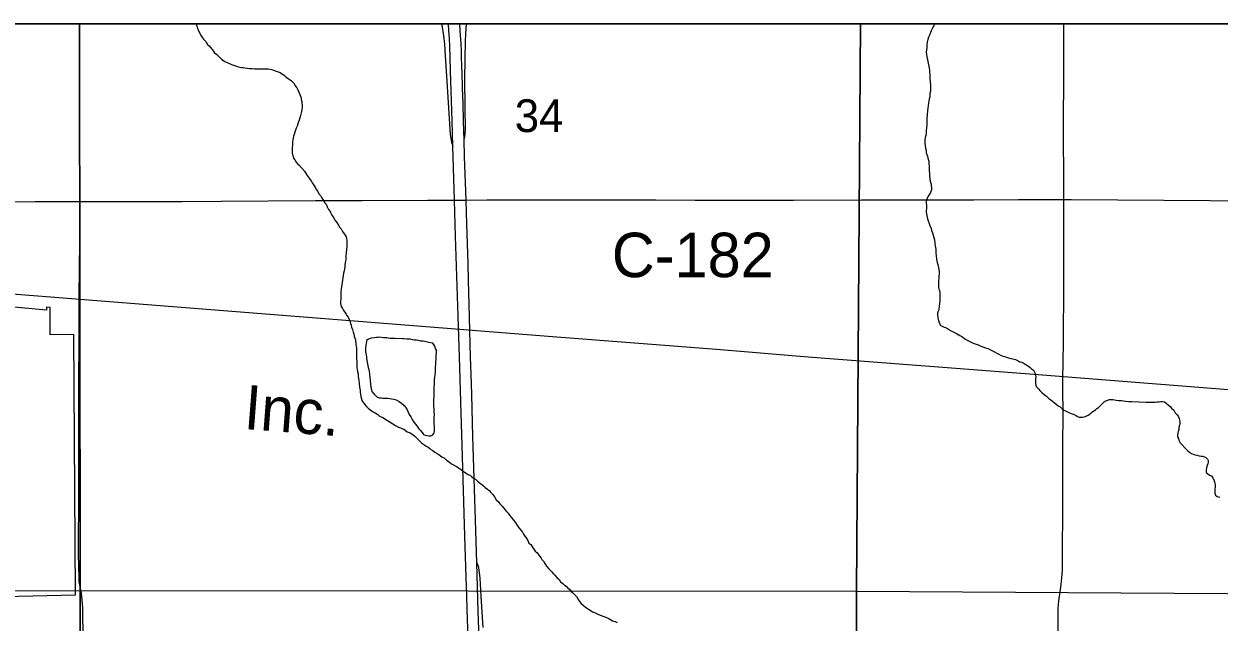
# Model space of a CAD drawing. Extents: x -17 to 88, y -5 to 22.
# Drawn here: x 5.65 to 7.178, y 20.136 to 20.9 of the extents above; entities that cross this region are included whole.
import ezdxf

# ---------------------------------------------------------------- set-up
doc = ezdxf.new("R2010")
doc.units = 0
for name, color, linetype in [('GM_X_Corporation', 7, 'Continuous'), ('GM_X_County_Road', 7, 'Continuous'), ('GM_X_County_Road_Text', 7, 'Continuous'), ('GM_X_Interchange_Ramps', 7, 'Continuous'), ('GM_X_Minor_Lake', 7, 'Continuous'), ('GM_X_Minor_River', 7, 'Continuous'), ('GM_X_Rail_Line', 7, 'Continuous'), ('GM_X_Rail_Line_Text', 7, 'Continuous'), ('GM_X_Section', 7, 'Continuous'), ('GM_X_Section_Text', 7, 'Continuous'), ('GM_X_Township', 7, 'Continuous'), ('GM_X_Township_Road', 7, 'Continuous'), ('GM_X_US_Route', 7, 'Continuous'), ('SH_Data', 7, 'Continuous')]:
    doc.layers.add(name, color=color, linetype=linetype)

msp = doc.modelspace()

# ---------------------------------------------------------------- linework, layer by layer
at = {"layer": 'GM_X_Corporation'}
msp.add_lwpolyline([(5.443, 20.164), (5.7163, 20.1707), (5.7142, 20.5031), (5.6839, 20.5029), (5.6839, 20.5377), (5.6792, 20.5381), (5.6792, 20.5343), (5.5358, 20.5474)], dxfattribs=at)
at = {"layer": 'GM_X_County_Road'}
for points in [[(5.5874, 20.6724), (5.665, 20.6729), (5.7221, 20.6729)], [(5.7221, 20.6729), (5.7678, 20.673), (5.8123, 20.6732), (5.8529, 20.6732), (5.9026, 20.6734), (6.0231, 20.6743), (6.0828, 20.6742), (6.1663, 20.6748), (6.2009, 20.6749), (6.2155, 20.675), (6.242, 20.6752), (6.2872, 20.6753), (6.3838, 20.6751), (6.4581, 20.6751), (6.5085, 20.6748), (6.5557, 20.6747), (6.634, 20.6747), (6.7207, 20.6753), (6.7882, 20.6753), (6.8646, 20.6754), (6.9217, 20.6755), (6.9796, 20.6755)], [(6.9796, 20.6755), (6.9889, 20.6755), (7.0485, 20.6752), (7.1659, 20.6744), (7.2076, 20.6741), (7.2512, 20.6738), (7.3034, 20.6736), (7.3543, 20.6734), (7.4103, 20.6735), (7.5085, 20.6729), (7.5401, 20.6726), (7.5694, 20.6725), (7.6306, 20.6723), (7.6964, 20.6717), (7.721, 20.6718)]]:
    msp.add_lwpolyline(points, dxfattribs=at)
at = {"layer": 'GM_X_Interchange_Ramps'}
for points in [[(6.1842, 20.9), (6.1846, 20.8983), (6.1866, 20.8848), (6.1878, 20.8743), (6.189, 20.8594), (6.1905, 20.8334), (6.1952, 20.7586), (6.196, 20.7535), (6.1969, 20.7489), (6.1987, 20.7439)], [(6.2129, 20.7517), (6.214, 20.7555), (6.2145, 20.7595), (6.2149, 20.7657), (6.2144, 20.7927), (6.2141, 20.8298), (6.2141, 20.8381), (6.2142, 20.8468), (6.2143, 20.8555), (6.2145, 20.8632), (6.2148, 20.8704), (6.215, 20.8779), (6.2154, 20.8872), (6.216, 20.9)]]:
    msp.add_lwpolyline(points, dxfattribs=at)
at = {"layer": 'GM_X_Minor_Lake'}
for points in [[(6.1046, 20.4221), (6.1069, 20.4221), (6.1092, 20.422), (6.1111, 20.4216), (6.113, 20.4216), (6.1153, 20.4216), (6.1179, 20.4215), (6.1202, 20.4211), (6.1232, 20.4206), (6.1251, 20.4199), (6.127, 20.4191), (6.13, 20.4175), (6.133, 20.4155), (6.1364, 20.4124), (6.139, 20.409), (6.1401, 20.407), (6.1416, 20.404), (6.143, 20.4009), (6.1449, 20.3978), (6.1467, 20.3944), (6.1489, 20.3913), (6.1515, 20.3882), (6.1534, 20.3852), (6.1552, 20.3828), (6.1567, 20.3809), (6.1593, 20.3778), (6.1612, 20.3755), (6.1631, 20.3747), (6.168, 20.3735), (6.1707, 20.3738), (6.173, 20.3749), (6.1749, 20.3775), (6.1753, 20.3794), (6.1754, 20.3813), (6.175, 20.3844), (6.1751, 20.3866), (6.1747, 20.3889), (6.1748, 20.3935), (6.1749, 20.3958), (6.1749, 20.398), (6.175, 20.4007), (6.1746, 20.4045), (6.1747, 20.4064), (6.1747, 20.4087), (6.1744, 20.411), (6.1744, 20.4132), (6.1745, 20.4167), (6.1745, 20.4189), (6.1742, 20.4212), (6.1746, 20.4231), (6.1747, 20.4254), (6.1747, 20.4288), (6.1748, 20.4315), (6.1748, 20.4334), (6.1754, 20.4421), (6.1754, 20.4459), (6.1758, 20.4482), (6.1759, 20.4516), (6.1764, 20.455), (6.1764, 20.4588), (6.1765, 20.4618), (6.1769, 20.4648), (6.177, 20.4683), (6.1774, 20.4713), (6.1775, 20.4743), (6.1775, 20.4766), (6.1776, 20.4793), (6.1776, 20.4831), (6.1765, 20.4854), (6.1755, 20.4884), (6.1729, 20.4919), (6.1702, 20.4927), (6.1679, 20.4931), (6.1645, 20.4939), (6.1626, 20.4943), (6.1607, 20.4948), (6.1577, 20.4948), (6.1547, 20.4953), (6.152, 20.4961), (6.1494, 20.4961), (6.1475, 20.4965), (6.1444, 20.497), (6.1422, 20.497), (6.1399, 20.4974), (6.1361, 20.4975), (6.1338, 20.4975), (6.1247, 20.4981), (6.1228, 20.4981), (6.1209, 20.4982), (6.1186, 20.4982), (6.116, 20.4986), (6.1141, 20.499), (6.1118, 20.4991), (6.1099, 20.4991), (6.1072, 20.4992), (6.1053, 20.4996), (6.103, 20.4993), (6.1011, 20.4993), (6.0981, 20.499), (6.0943, 20.4983), (6.0889, 20.4965)], [(6.0889, 20.4965), (6.0873, 20.4897), (6.0868, 20.4855), (6.0872, 20.4836), (6.0871, 20.4809), (6.0878, 20.4771), (6.0881, 20.4745), (6.0885, 20.4726), (6.0902, 20.463), (6.0905, 20.4608), (6.0913, 20.4585), (6.0916, 20.4558), (6.0923, 20.4524), (6.0926, 20.4482), (6.0929, 20.444), (6.0932, 20.4398), (6.0939, 20.436), (6.0946, 20.433), (6.0953, 20.4303), (6.0979, 20.4268), (6.1016, 20.4233), (6.1046, 20.4221)]]:
    msp.add_lwpolyline(points, dxfattribs=at)
at = {"layer": 'GM_X_Minor_River'}
for points in [[(5.8706, 20.9), (5.871, 20.8981), (5.8717, 20.8962), (5.8724, 20.8943), (5.8731, 20.8924), (5.8739, 20.8905), (5.8772, 20.8847), (5.8787, 20.8824), (5.8801, 20.8805), (5.8828, 20.8774), (5.8853, 20.8739), (5.8872, 20.872), (5.8891, 20.8697), (5.8913, 20.867), (5.8939, 20.8631), (5.8969, 20.8608), (5.8995, 20.8585), (5.9017, 20.8562), (5.9036, 20.8546), (5.9055, 20.8534), (5.9074, 20.8519), (5.9093, 20.8511), (5.9111, 20.8503), (5.913, 20.8495), (5.9157, 20.8483), (5.9183, 20.8471), (5.9221, 20.8459), (5.9243, 20.8451), (5.9266, 20.8447), (5.9285, 20.8443), (5.9308, 20.8442), (5.9327, 20.8438), (5.9357, 20.8434), (5.9388, 20.8429), (5.9422, 20.8429), (5.9456, 20.8424), (5.949, 20.8424), (5.9524, 20.8427), (5.957, 20.8426), (5.96, 20.8425), (5.9627, 20.8425), (5.965, 20.8421), (5.9672, 20.8417), (5.9695, 20.8408), (5.9714, 20.8401), (5.974, 20.8392), (5.9778, 20.8377), (5.9797, 20.8365), (5.9816, 20.8353), (5.9835, 20.8341), (5.9853, 20.8322), (5.9924, 20.8271), (5.9954, 20.8244), (5.9976, 20.8206)], [(6.8143, 20.9), (6.8143, 20.9), (6.8131, 20.8977), (6.8119, 20.8958), (6.8111, 20.8936), (6.8099, 20.8913), (6.8091, 20.889), (6.8079, 20.8857), (6.8063, 20.883), (6.8055, 20.88), (6.8047, 20.8766), (6.8043, 20.8732), (6.8042, 20.8698), (6.8038, 20.8667), (6.8037, 20.8641), (6.804, 20.861), (6.8044, 20.858), (6.805, 20.8542), (6.8061, 20.85), (6.8068, 20.8458), (6.8075, 20.8431), (6.8078, 20.8412), (6.8078, 20.8386), (6.8081, 20.8351), (6.8081, 20.8325), (6.8084, 20.8298), (6.8087, 20.826), (6.809, 20.8222), (6.8089, 20.8188), (6.8089, 20.8165), (6.8089, 20.8142), (6.8084, 20.8116), (6.8084, 20.8093), (6.808, 20.807), (6.8075, 20.8044), (6.8071, 20.8017), (6.8067, 20.7991), (6.8062, 20.7957), (6.8058, 20.7923), (6.8054, 20.7892), (6.8044, 20.7786), (6.8043, 20.7748), (6.8043, 20.771), (6.8038, 20.7672), (6.8037, 20.7638), (6.8033, 20.7604), (6.8029, 20.7574), (6.8024, 20.7547), (6.802, 20.7525), (6.802, 20.7498), (6.8019, 20.7472), (6.8022, 20.7441), (6.8026, 20.7414), (6.8033, 20.7384), (6.8036, 20.7354), (6.8043, 20.7331), (6.805, 20.7311), (6.8057, 20.7285), (6.8068, 20.7247), (6.8071, 20.7212), (6.8074, 20.7178), (6.8074, 20.7152), (6.8073, 20.7117)], [(5.9976, 20.8206), (5.9991, 20.8183), (6.0006, 20.8156), (6.0017, 20.8129), (6.0032, 20.8098), (6.0039, 20.8076), (6.0046, 20.8056), (6.0049, 20.8034), (6.0056, 20.8007), (6.0056, 20.7988), (6.0059, 20.7965), (6.0059, 20.7938), (6.0058, 20.7904), (6.0054, 20.7882), (6.005, 20.7863), (6.0038, 20.7829), (6.003, 20.7802), (6.0022, 20.7772), (6.0014, 20.7749), (6.0005, 20.7723), (5.9997, 20.7693), (5.9985, 20.7666), (5.9974, 20.7644), (5.9965, 20.7617), (5.9957, 20.7587), (5.9949, 20.7565), (5.9945, 20.7538), (5.9941, 20.7515), (5.9937, 20.7496), (5.9936, 20.7474), (5.9936, 20.7447), (5.9935, 20.742), (5.9931, 20.7394), (5.9931, 20.7375), (5.9934, 20.7348), (5.9944, 20.7306), (5.9952, 20.7283), (5.9967, 20.7264), (5.9985, 20.7233), (6.0004, 20.721), (6.0022, 20.7195), (6.0089, 20.7118), (6.0104, 20.7098), (6.0126, 20.7064), (6.0141, 20.7041), (6.016, 20.7018), (6.0174, 20.6995), (6.0189, 20.6971), (6.02, 20.6952), (6.0215, 20.6929), (6.023, 20.6906), (6.0241, 20.6883), (6.0259, 20.686), (6.0274, 20.6829), (6.0293, 20.6806), (6.0307, 20.6783), (6.0322, 20.676), (6.0337, 20.6741), (6.0348, 20.6718), (6.0366, 20.6695), (6.0381, 20.6664), (6.0396, 20.663), (6.0418, 20.6603), (6.0429, 20.6583), (6.044, 20.6557), (6.0455, 20.6537), (6.0473, 20.6507), (6.0484, 20.6487), (6.0503, 20.6461), (6.0525, 20.643), (6.0543, 20.6399), (6.0558, 20.638), (6.0577, 20.6349), (6.0599, 20.6318), (6.061, 20.6299), (6.0621, 20.628), (6.0628, 20.6257), (6.0632, 20.6234), (6.063, 20.6154), (6.0626, 20.612), (6.0621, 20.6075), (6.062, 20.6033), (6.0619, 20.5984), (6.0611, 20.595), (6.0607, 20.5923), (6.0606, 20.5893), (6.0602, 20.587), (6.0598, 20.5847), (6.059, 20.5817), (6.0585, 20.5787), (6.0581, 20.5757), (6.0577, 20.5726), (6.0572, 20.5696), (6.0568, 20.5666), (6.0564, 20.5643), (6.0559, 20.5613), (6.0555, 20.5579), (6.0554, 20.5556), (6.0554, 20.5533), (6.0553, 20.5506), (6.0553, 20.548)], [(6.8073, 20.7117), (6.8077, 20.7091), (6.8076, 20.7057), (6.8083, 20.7022), (6.8086, 20.6992), (6.8097, 20.6954), (6.81, 20.6931), (6.8104, 20.6908), (6.8103, 20.6881), (6.8091, 20.6844), (6.8068, 20.681), (6.8052, 20.678), (6.8044, 20.6761), (6.8036, 20.6731), (6.8035, 20.6712), (6.8038, 20.6678), (6.8038, 20.6643), (6.8037, 20.6617), (6.8037, 20.6598), (6.804, 20.6575), (6.8054, 20.651), (6.8061, 20.6483), (6.8072, 20.6449), (6.8083, 20.6418), (6.8098, 20.6392), (6.8105, 20.6361), (6.8116, 20.6331), (6.8123, 20.63), (6.8134, 20.6273), (6.814, 20.6239), (6.8147, 20.6197), (6.815, 20.6163), (6.8157, 20.6121), (6.816, 20.6075), (6.8163, 20.6033), (6.8166, 20.5999), (6.8173, 20.5969), (6.818, 20.5938), (6.8188, 20.5915), (6.8191, 20.5881), (6.8198, 20.5858), (6.8201, 20.5835), (6.8201, 20.5809), (6.8196, 20.5775), (6.8196, 20.5748), (6.8192, 20.5721), (6.8191, 20.5691), (6.8191, 20.5665), (6.8194, 20.5638), (6.8197, 20.5611), (6.8204, 20.5592), (6.8208, 20.5566), (6.8211, 20.552), (6.821, 20.5493), (6.821, 20.5463), (6.8205, 20.5429), (6.8201, 20.5391), (6.8196, 20.5357), (6.8192, 20.5338), (6.8184, 20.5319), (6.818, 20.53), (6.818, 20.5277), (6.8183, 20.5247), (6.819, 20.5224), (6.8197, 20.5197), (6.8219, 20.5148), (6.8238, 20.5136), (6.8264, 20.5124), (6.8283, 20.512), (6.8306, 20.5108), (6.8347, 20.5084), (6.8388, 20.5061), (6.8422, 20.5045), (6.8445, 20.5033), (6.8467, 20.5018), (6.849, 20.5006), (6.8509, 20.4994), (6.8531, 20.4978), (6.8561, 20.4959), (6.8595, 20.4943), (6.8629, 20.4927), (6.8663, 20.4911), (6.8701, 20.4899), (6.8727, 20.4888), (6.8758, 20.4876), (6.8795, 20.4863), (6.8826, 20.4851), (6.8856, 20.4836), (6.8882, 20.4824), (6.8908, 20.4808), (6.8938, 20.4792), (6.8965, 20.4781), (6.8995, 20.4765), (6.9048, 20.4745), (6.9086, 20.4733), (6.9116, 20.4725), (6.9142, 20.472), (6.9176, 20.4712), (6.921, 20.4696), (6.9233, 20.4684), (6.9256, 20.4676)], [(6.0553, 20.548), (6.0552, 20.5453), (6.0552, 20.5427), (6.0559, 20.5389), (6.0577, 20.5362), (6.0588, 20.5339), (6.0607, 20.5316), (6.0625, 20.5292), (6.0633, 20.5273), (6.0648, 20.5254), (6.0673, 20.5193), (6.068, 20.5174), (6.0687, 20.5151), (6.0691, 20.5124), (6.0702, 20.5094), (6.0712, 20.5063), (6.072, 20.504), (6.0727, 20.501), (6.0734, 20.4983), (6.0741, 20.4964), (6.0744, 20.4945), (6.0748, 20.4926), (6.0747, 20.4903), (6.0751, 20.488), (6.0754, 20.4861), (6.0754, 20.4834), (6.0753, 20.4808), (6.0756, 20.4777), (6.0756, 20.4751), (6.0755, 20.472), (6.0759, 20.4694), (6.0758, 20.4663), (6.0758, 20.4637), (6.0761, 20.4606), (6.0764, 20.4587), (6.0768, 20.4557), (6.0775, 20.453), (6.0778, 20.4511), (6.0778, 20.4492), (6.0781, 20.4469), (6.0785, 20.4446), (6.0788, 20.4405), (6.0794, 20.4359), (6.0801, 20.4317), (6.0804, 20.429), (6.0808, 20.4268), (6.0811, 20.4241), (6.0818, 20.421), (6.0825, 20.4187), (6.0859, 20.4141), (6.0885, 20.411), (6.0903, 20.4091), (6.0922, 20.4079), (6.0948, 20.4056), (6.0967, 20.4044), (6.0993, 20.4029), (6.1027, 20.4009), (6.105, 20.399), (6.1072, 20.3978), (6.1099, 20.3966), (6.1117, 20.3954), (6.1151, 20.3931), (6.1185, 20.3911), (6.1219, 20.3892), (6.1253, 20.3868), (6.129, 20.3848), (6.1317, 20.3837), (6.1336, 20.3829), (6.1358, 20.3821), (6.1377, 20.3809), (6.1403, 20.3789), (6.1441, 20.3774), (6.1464, 20.3762), (6.1501, 20.3731), (6.1535, 20.37), (6.1557, 20.3676), (6.1583, 20.3653), (6.1602, 20.3634), (6.1628, 20.3618), (6.1647, 20.3606), (6.167, 20.3591), (6.1688, 20.3579), (6.1707, 20.3564), (6.173, 20.3548), (6.1756, 20.3528), (6.1786, 20.3513), (6.1812, 20.3493), (6.1846, 20.347), (6.188, 20.345), (6.1906, 20.3427), (6.194, 20.3403), (6.197, 20.338), (6.2041, 20.3341), (6.2071, 20.3321), (6.2098, 20.3302), (6.212, 20.3286), (6.215, 20.3263), (6.218, 20.3243), (6.221, 20.3228), (6.2229, 20.3212), (6.2248, 20.32)], [(6.9256, 20.4676), (6.9275, 20.4668), (6.9301, 20.4653), (6.932, 20.4641), (6.9342, 20.4629), (6.9365, 20.461), (6.9387, 20.459), (6.9406, 20.4575), (6.9421, 20.4552), (6.9428, 20.4533), (6.9431, 20.4514), (6.9435, 20.4491), (6.9434, 20.446), (6.9433, 20.4422), (6.9433, 20.4404), (6.9437, 20.4384), (6.9447, 20.4361), (6.9474, 20.4334), (6.9488, 20.4315), (6.9515, 20.4292), (6.9541, 20.4265), (6.9571, 20.4245), (6.9604, 20.4214), (6.9627, 20.4195), (6.9649, 20.4179), (6.9672, 20.4164), (6.9698, 20.414), (6.9724, 20.4121), (6.9747, 20.4109), (6.9777, 20.4078), (6.9796, 20.4066), (6.9814, 20.4055), (6.9848, 20.4039), (6.9867, 20.4031), (6.9886, 20.4023), (6.9912, 20.4015), (6.995, 20.3995), (6.9969, 20.3983), (6.9992, 20.3975), (7.0011, 20.3975), (7.003, 20.3975), (7.0056, 20.3978), (7.0087, 20.3993), (7.0106, 20.4), (7.0129, 20.4018), (7.0149, 20.4033), (7.0176, 20.4056), (7.0199, 20.407), (7.0218, 20.4085), (7.0237, 20.41), (7.0264, 20.4126), (7.0288, 20.4152), (7.0315, 20.4174), (7.0345, 20.4189), (7.038, 20.42), (7.0403, 20.4199), (7.0422, 20.4199), (7.0463, 20.4194), (7.0494, 20.419), (7.0532, 20.4189), (7.0558, 20.4185), (7.0588, 20.4181), (7.0623, 20.4176), (7.0664, 20.4176), (7.0843, 20.4165), (7.0889, 20.4168), (7.0915, 20.4167), (7.0934, 20.4167), (7.0961, 20.4166), (7.0987, 20.417), (7.1007, 20.4173), (7.1033, 20.4176), (7.1056, 20.4176), (7.1079, 20.4172), (7.1101, 20.4156), (7.1131, 20.4129), (7.1154, 20.411), (7.1172, 20.409), (7.1198, 20.4063), (7.1217, 20.4032), (7.1243, 20.4005), (7.1261, 20.3978), (7.1269, 20.3959), (7.1272, 20.394), (7.1275, 20.3917), (7.1275, 20.3895), (7.1271, 20.3872), (7.1266, 20.3842), (7.1262, 20.3819), (7.1254, 20.3792), (7.125, 20.377), (7.1246, 20.3751), (7.1249, 20.3724), (7.126, 20.3701), (7.1263, 20.3682), (7.1282, 20.3648), (7.136, 20.3563), (7.1379, 20.3547), (7.1401, 20.3528), (7.1424, 20.3512), (7.1469, 20.3492)], [(7.1469, 20.3492), (7.1496, 20.3488), (7.1522, 20.348), (7.1549, 20.3479), (7.1568, 20.3475), (7.159, 20.3467), (7.1609, 20.3459), (7.1632, 20.344), (7.1639, 20.3421), (7.1638, 20.3402), (7.1634, 20.3379), (7.1626, 20.3356), (7.1618, 20.333), (7.1614, 20.3296), (7.1613, 20.3269), (7.1632, 20.3254), (7.1654, 20.3234), (7.1681, 20.3226), (7.1699, 20.3199), (7.1714, 20.3161), (7.1725, 20.3138), (7.1728, 20.3112), (7.1728, 20.3085), (7.1723, 20.3051), (7.1723, 20.3028), (7.1722, 20.3005), (7.1733, 20.2979), (7.1752, 20.2963), (7.1786, 20.2951)], [(6.2248, 20.32), (6.2274, 20.3181), (6.23, 20.3158), (6.2326, 20.3138), (6.2353, 20.3119), (6.2379, 20.3099), (6.2401, 20.3076), (6.2428, 20.3056), (6.245, 20.3037), (6.2469, 20.3018), (6.2491, 20.2991), (6.2517, 20.2956), (6.2539, 20.2918), (6.2565, 20.2898), (6.2587, 20.2867), (6.2617, 20.2836), (6.2632, 20.2817), (6.2651, 20.2794), (6.2673, 20.2771), (6.2692, 20.2748), (6.271, 20.2725), (6.2733, 20.2698), (6.2762, 20.2659), (6.2781, 20.2632), (6.2803, 20.2601), (6.2829, 20.2563), (6.2859, 20.2528), (6.2877, 20.2505), (6.2888, 20.2482), (6.2907, 20.2455), (6.2922, 20.2432), (6.2944, 20.2398), (6.2958, 20.2367), (6.2981, 20.2347), (6.2996, 20.2328), (6.3022, 20.229), (6.304, 20.2263), (6.3059, 20.2244), (6.3114, 20.2174), (6.3125, 20.2155), (6.3144, 20.2136), (6.3163, 20.2105), (6.3185, 20.207), (6.3214, 20.2039), (6.3233, 20.2016), (6.3252, 20.2001), (6.3267, 20.1978), (6.3285, 20.1962), (6.3315, 20.1927), (6.3345, 20.19), (6.336, 20.1873), (6.339, 20.185), (6.3412, 20.1827), (6.3435, 20.1815), (6.3457, 20.1792), (6.3476, 20.1776), (6.3498, 20.1749), (6.3517, 20.1734), (6.3539, 20.1711), (6.3565, 20.1683), (6.3584, 20.1653), (6.3606, 20.1622), (6.3628, 20.1595), (6.3654, 20.1568), (6.3677, 20.1552), (6.3696, 20.1541), (6.3722, 20.1521), (6.3752, 20.1502), (6.3771, 20.149), (6.379, 20.1482), (6.3812, 20.147), (6.3846, 20.1454), (6.3948, 20.1414), (6.3971, 20.1406), (6.3993, 20.1395), (6.4027, 20.1375), (6.4061, 20.1363), (6.4087, 20.1351)]]:
    msp.add_lwpolyline(points, dxfattribs=at)
at = {"layer": 'GM_X_Rail_Line'}
msp.add_lwpolyline([(3.3378, 20.6349), (3.4243, 20.6351), (3.6677, 20.6333), (4.0499, 20.6291), (4.4114, 20.6255), (4.6971, 20.6224), (4.7817, 20.6203), (4.8312, 20.6178), (4.878, 20.6147), (5.0238, 20.6032), (5.3556, 20.5774), (5.532, 20.5632), (5.6305, 20.5554), (5.7167, 20.5487), (6.326, 20.5007), (6.5355, 20.4843), (6.6527, 20.4747), (6.952, 20.4515), (7.2707, 20.4266), (7.4596, 20.412), (8.1711, 20.3564), (8.7312, 20.3127), (9.0583, 20.2871), (9.4, 20.2603)], dxfattribs=at)
at = {"layer": 'GM_X_Section'}
for p, q in [((5.7214, 20.9), (4.7118, 20.9)), ((6.7198, 20.9), (5.7214, 20.9)), ((7.7301, 20.9), (6.7198, 20.9))]:
    msp.add_line(p, q, dxfattribs=at)
for points in [[(4.7118, 20.9), (4.7146, 20.1753), (5.7223, 20.1762), (5.7214, 20.9)], [(5.7214, 20.9), (5.7223, 20.1762), (6.7146, 20.1751), (6.7198, 20.9)], [(6.7198, 20.9), (6.7146, 20.1751), (7.7295, 20.169), (7.7301, 20.9)]]:
    msp.add_lwpolyline(points, dxfattribs=at)
for points in [[(5.7223, 20.1762), (5.7206, 19.1483), (4.7297, 19.1567), (4.7146, 20.1753)], [(6.7146, 20.1751), (6.7133, 19.1594), (5.7206, 19.1483), (5.7223, 20.1762)], [(6.7146, 20.1751), (7.7295, 20.169), (7.7351, 19.1493), (6.7133, 19.1594)]]:
    msp.add_lwpolyline(points, close=True, dxfattribs=at)
at = {"layer": 'GM_X_Township'}
msp.add_line((7.7218, 20.9), (2.6882, 20.9), dxfattribs=at)
at = {"layer": 'GM_X_Township_Road'}
for points in [[(6.9796, 20.6755), (6.9796, 20.679), (6.9792, 20.7814), (6.9793, 20.8243), (6.9793, 20.8634), (6.9795, 20.9)], [(5.7212, 20.503), (5.7213, 20.5576), (5.7215, 20.5824), (5.7218, 20.6267), (5.7221, 20.6729)], [(6.9705, 19.9069), (6.9709, 19.9441), (6.9718, 19.9994), (6.972, 20.0373), (6.9719, 20.0982), (6.9721, 20.1429), (6.9722, 20.1474), (6.9724, 20.1527), (6.9727, 20.1576), (6.9732, 20.1627), (6.9753, 20.1774), (6.9762, 20.1839), (6.977, 20.1923), (6.9776, 20.2017), (6.9778, 20.2103), (6.9782, 20.2936), (6.9783, 20.3694), (6.9784, 20.3936), (6.9782, 20.4427), (6.9786, 20.471), (6.9789, 20.4906), (6.9794, 20.5701), (6.9794, 20.6267), (6.9796, 20.6755)], [(5.724, 20.1726), (5.7226, 20.1788), (5.7218, 20.1831), (5.7212, 20.1875), (5.721, 20.193), (5.7203, 20.2217), (5.7206, 20.3049), (5.7206, 20.3565), (5.7208, 20.4341), (5.7212, 20.503)], [(5.7249, 19.9013), (5.7254, 19.9491), (5.7255, 20.0068), (5.7256, 20.0546), (5.726, 20.1192), (5.7256, 20.1478), (5.7257, 20.1543), (5.7251, 20.1636), (5.7247, 20.1683), (5.724, 20.1726)]]:
    msp.add_lwpolyline(points, dxfattribs=at)
at = {"layer": 'GM_X_US_Route'}
for points in [[(6.218, 20.1157), (6.217, 20.1517), (6.2164, 20.1697), (6.2155, 20.1932), (6.214, 20.2454), (6.2105, 20.3616), (6.209, 20.4169), (6.2076, 20.461), (6.2058, 20.5138), (6.2038, 20.5778), (6.2022, 20.6288), (6.2009, 20.6749), (6.1987, 20.7439), (6.1976, 20.776), (6.1957, 20.8399), (6.1952, 20.858), (6.1947, 20.8707), (6.1942, 20.8818), (6.1936, 20.8911), (6.193, 20.9)], [(6.2085, 20.8857), (6.2082, 20.891), (6.2076, 20.9)], [(6.2111, 20.8177), (6.211, 20.822), (6.2102, 20.8476), (6.2099, 20.8564), (6.2096, 20.8648), (6.2091, 20.8749), (6.2085, 20.8857)], [(6.2117, 20.7987), (6.2111, 20.8177)], [(6.216, 20.6587), (6.2155, 20.675), (6.2134, 20.7307), (6.2129, 20.7517), (6.2123, 20.7754), (6.2117, 20.7987)], [(6.2186, 20.5726), (6.218, 20.5935), (6.2164, 20.645), (6.216, 20.6587)], [(6.2219, 20.4525), (6.2213, 20.4742), (6.2198, 20.5251), (6.2186, 20.5726)], [(6.2292, 20.2114), (6.2275, 20.2662), (6.2243, 20.3724), (6.2227, 20.4264), (6.2219, 20.4525)], [(6.2321, 20.1144), (6.2308, 20.1495), (6.2292, 20.2114)], [(6.2292, 20.2114), (6.231, 20.2073), (6.232, 20.2026), (6.2332, 20.1917), (6.2346, 20.169), (6.2369, 20.1287)]]:
    msp.add_lwpolyline(points, dxfattribs=at)
at = {"layer": 'SH_Data'}
msp.add_line((2.6, 20.9), (9.4, 20.9), dxfattribs=at)

# ---------------------------------------------------------------- texts
at = {"layer": 'GM_X_County_Road_Text'}
msp.add_text('C-182', height=0.05682, rotation=0, dxfattribs=at).set_placement((6.4018, 20.5764))
at = {"layer": 'GM_X_Rail_Line_Text'}
msp.add_text('Inc.', height=0.05663, rotation=355.627, dxfattribs=at).set_placement((5.9305, 20.3825))
at = {"layer": 'GM_X_Section_Text'}
msp.add_text('34', height=0.04186, rotation=0, dxfattribs=at).set_placement((6.2777, 20.7618))

doc.saveas('drawing.dxf')
